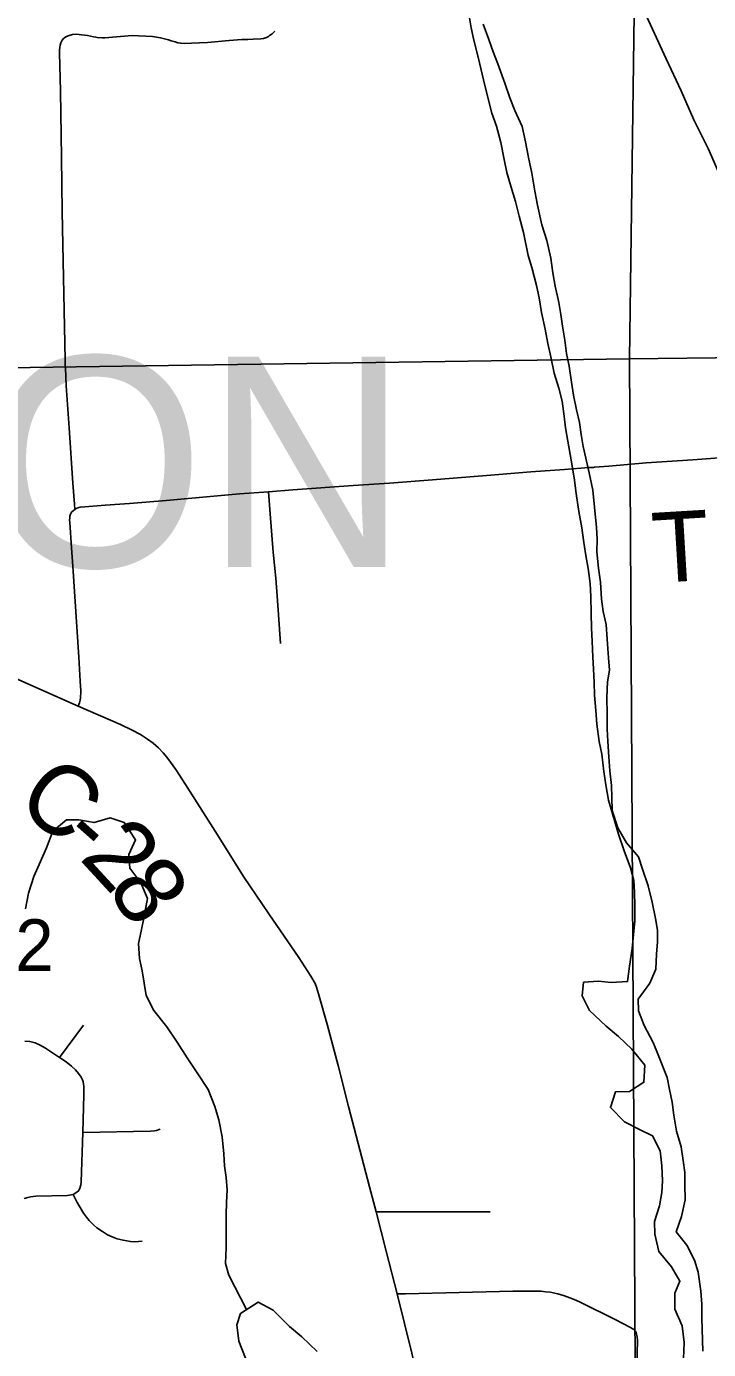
# Model space of a CAD drawing. Extents: x -87 to 2145, y -2128 to 440.
# Drawn here: x -42.301 to -41.749, y -694.892 to -693.821 of the extents above; entities that cross this region are included whole.
import ezdxf

# ---------------------------------------------------------------- set-up
doc = ezdxf.new("R2010")
doc.units = 0
for name, color, linetype in [('GM_X_City_Street', 7, 'Continuous'), ('GM_X_County_Road', 7, 'Continuous'), ('GM_X_County_Road_Text', 7, 'Continuous'), ('GM_X_Minor_Lake', 7, 'Continuous'), ('GM_X_Minor_River', 7, 'Continuous'), ('GM_X_Section', 7, 'Continuous'), ('GM_X_Section_Text', 7, 'Continuous'), ('GM_X_State_Route', 7, 'Continuous'), ('GM_X_Township_Road', 7, 'Continuous'), ('GM_X_Township_Road_Text', 7, 'Continuous'), ('GM_X_Township_Text', 7, 'Continuous')]:
    doc.layers.add(name, color=color, linetype=linetype)

msp = doc.modelspace()

# ---------------------------------------------------------------- linework, layer by layer
at = {"layer": 'GM_X_City_Street'}
msp.add_line((-42.2744, -694.656), (-42.2552, -694.6298), dxfattribs=at)
for points in [[(-42.3026, -694.6427), (-42.2985, -694.643), (-42.2942, -694.6441), (-42.2906, -694.6456), (-42.2858, -694.6483), (-42.2744, -694.656), (-42.2692, -694.6595), (-42.2648, -694.663), (-42.2616, -694.666), (-42.2592, -694.6688), (-42.257, -694.6717), (-42.2559, -694.6739), (-42.2553, -694.6757), (-42.2549, -694.6794), (-42.2549, -694.6862), (-42.2557, -694.7167), (-42.257, -694.7565), (-42.2573, -694.7591), (-42.258, -694.7616), (-42.259, -694.7635), (-42.2606, -694.765), (-42.2634, -694.7667), (-42.268, -694.7676), (-42.2937, -694.7683), (-42.298, -694.7687), (-42.3003, -694.7692), (-42.3031, -694.7702)], [(-42.2557, -694.7167), (-42.2008, -694.7156), (-42.1977, -694.7154), (-42.1959, -694.715), (-42.1931, -694.7139)], [(-42.2634, -694.7667), (-42.2601, -694.7733), (-42.2579, -694.7774), (-42.2552, -694.782), (-42.2528, -694.7851), (-42.2504, -694.7878), (-42.2471, -694.7913), (-42.2443, -694.7937), (-42.2398, -694.7969), (-42.2356, -694.7994), (-42.2318, -694.8012), (-42.2278, -694.8027), (-42.223, -694.8039), (-42.217, -694.8049), (-42.2134, -694.8051), (-42.2106, -694.805), (-42.2077, -694.8045)], [(-42.0182, -694.7808), (-42.0053, -694.7808), (-41.9257, -694.7809)], [(-42.0012, -694.8474), (-41.9944, -694.8473), (-41.9075, -694.8451), (-41.8889, -694.845), (-41.8846, -694.8452), (-41.881, -694.8456), (-41.8771, -694.846), (-41.871, -694.8473), (-41.8657, -694.8489), (-41.8613, -694.8506), (-41.8564, -694.8525), (-41.8525, -694.8544), (-41.8246, -694.8681), (-41.8121, -694.8745), (-41.8095, -694.8762)], [(-41.8072, -694.9165), (-41.8064, -694.8847), (-41.8067, -694.882), (-41.8072, -694.88), (-41.8076, -694.8787), (-41.8082, -694.8776), (-41.8095, -694.8762)]]:
    msp.add_lwpolyline(points, dxfattribs=at)
at = {"layer": 'GM_X_County_Road'}
for points in [[(-42.3424, -694.3346), (-42.2952, -694.3554), (-42.2593, -694.3714)], [(-42.2593, -694.3714), (-42.2252, -694.3863), (-42.2158, -694.3908), (-42.209, -694.3943), (-42.2032, -694.398), (-42.1987, -694.4014), (-42.1944, -694.4052), (-42.1905, -694.4092), (-42.1876, -694.4126), (-42.1846, -694.4166), (-42.1804, -694.4227), (-42.1726, -694.4347), (-42.1466, -694.4757), (-42.1256, -694.5093), (-42.1049, -694.5395), (-42.0807, -694.5749), (-42.0709, -694.5901), (-42.0675, -694.596)], [(-42.0675, -694.596), (-42.0664, -694.5989), (-42.0647, -694.6043), (-42.0576, -694.6301), (-42.0489, -694.6625), (-42.0404, -694.6956), (-42.0234, -694.7605), (-42.0182, -694.7808)], [(-42.0182, -694.7808), (-42.0101, -694.8126), (-42.0012, -694.8474)], [(-42.0012, -694.8474), (-41.9832, -694.9193), (-41.9763, -694.9476), (-41.9744, -694.9554), (-41.973, -694.9594), (-41.9714, -694.9626), (-41.9697, -694.9651), (-41.9677, -694.9672), (-41.9664, -694.9684), (-41.9634, -694.9702), (-41.9595, -694.9718), (-41.9536, -694.9734), (-41.925, -694.979), (-41.9207, -694.9799), (-41.917, -694.9809), (-41.9105, -694.9831), (-41.9019, -694.9868), (-41.8288, -695.021)]]:
    msp.add_lwpolyline(points, dxfattribs=at)
at = {"layer": 'GM_X_Minor_Lake'}
for points in [[(-41.9432, -693.8108), (-41.9412, -693.8222), (-41.9391, -693.8321), (-41.9356, -693.8458), (-41.9311, -693.8642), (-41.9279, -693.8775), (-41.9244, -693.8912), (-41.9208, -693.9016), (-41.9173, -693.9149), (-41.9146, -693.9287), (-41.9122, -693.9393), (-41.909, -693.9504), (-41.9054, -693.9626), (-41.9023, -693.9745), (-41.8988, -693.9878), (-41.895, -694.0065), (-41.8921, -694.0161), (-41.8883, -694.0306), (-41.8862, -694.0408), (-41.8842, -694.0527), (-41.8814, -694.066), (-41.879, -694.0778), (-41.8766, -694.0885), (-41.8739, -694.1018), (-41.8703, -694.114), (-41.8675, -694.1244), (-41.8659, -694.1365), (-41.8649, -694.146), (-41.8629, -694.1567), (-41.8602, -694.1723), (-41.8578, -694.1864), (-41.8562, -694.1993), (-41.8539, -694.2138), (-41.8515, -694.2271), (-41.8502, -694.237), (-41.8485, -694.2477), (-41.8465, -694.2599), (-41.8449, -694.272), (-41.8444, -694.2827), (-41.8439, -694.296), (-41.8438, -694.3081), (-41.8433, -694.3187), (-41.8428, -694.3316), (-41.8422, -694.3411), (-41.8417, -694.3521), (-41.8412, -694.3624), (-41.8403, -694.3749), (-41.8394, -694.3859), (-41.8375, -694.4), (-41.8354, -694.4103), (-41.8338, -694.4244), (-41.8321, -694.435), (-41.8301, -694.4476), (-41.8266, -694.4594), (-41.822, -694.4751), (-41.8173, -694.4885), (-41.8123, -694.5023), (-41.8095, -694.5126), (-41.8089, -694.5221), (-41.8088, -694.5327), (-41.8087, -694.5452), (-41.8097, -694.5562), (-41.8107, -694.5675), (-41.8129, -694.5819), (-41.8147, -694.5944), (-41.8277, -694.5952), (-41.838, -694.5942), (-41.8502, -694.595), (-41.8512, -694.606), (-41.8453, -694.6179), (-41.8319, -694.6304), (-41.8218, -694.6389)], [(-41.7681, -694.759), (-41.7683, -694.7491), (-41.7696, -694.7392), (-41.7712, -694.7282), (-41.7748, -694.7156), (-41.7771, -694.7026), (-41.7784, -694.692), (-41.7805, -694.6817), (-41.7826, -694.6721), (-41.7898, -694.6538), (-41.7937, -694.6438), (-41.801, -694.63), (-41.8057, -694.6181), (-41.8059, -694.6086), (-41.7965, -694.5956), (-41.7917, -694.5843), (-41.791, -694.5722), (-41.7904, -694.5623), (-41.7902, -694.5529), (-41.7919, -694.5433), (-41.7946, -694.53), (-41.7978, -694.517), (-41.8024, -694.5033), (-41.8056, -694.4933), (-41.8153, -694.4821), (-41.8223, -694.4698), (-41.8269, -694.456), (-41.8274, -694.4454), (-41.8276, -694.4355), (-41.8288, -694.4237), (-41.8297, -694.4123), (-41.8306, -694.3998), (-41.8311, -694.3899), (-41.8312, -694.3778), (-41.8313, -694.3645), (-41.8307, -694.3516), (-41.8293, -694.3422), (-41.8299, -694.3323), (-41.831, -694.3171), (-41.8319, -694.3053), (-41.8344, -694.2947), (-41.8357, -694.2848), (-41.8365, -694.2711), (-41.8381, -694.2597), (-41.8394, -694.2464), (-41.8391, -694.2362), (-41.8397, -694.2267), (-41.8412, -694.2103), (-41.8428, -694.1966), (-41.8456, -694.1825), (-41.8504, -694.1612), (-41.8521, -694.1513), (-41.8534, -694.1418), (-41.8559, -694.1315), (-41.8583, -694.1196), (-41.8599, -694.109), (-41.8619, -694.096), (-41.864, -694.0858), (-41.8653, -694.0751), (-41.8673, -694.0637), (-41.8686, -694.0542), (-41.8703, -694.0446), (-41.8731, -694.0313), (-41.8751, -694.0206), (-41.8767, -694.0085), (-41.8799, -693.9943), (-41.8841, -693.9817), (-41.8876, -693.9657), (-41.8896, -693.9543), (-41.892, -693.9398), (-41.8947, -693.9272), (-41.8971, -693.9143), (-41.8999, -693.9021), (-41.9057, -693.889), (-41.91, -693.8787), (-41.914, -693.8668), (-41.9197, -693.8511), (-41.9233, -693.8416), (-41.9269, -693.8316), (-41.9316, -693.819)], [(-41.8218, -694.6389), (-41.811, -694.6491), (-41.8006, -694.6622), (-41.8013, -694.6759), (-41.8129, -694.6835), (-41.8243, -694.6836), (-41.8284, -694.6964), (-41.8169, -694.7081), (-41.8048, -694.7141), (-41.7943, -694.7193), (-41.7881, -694.7316), (-41.7868, -694.7437), (-41.7863, -694.7559), (-41.7869, -694.7653), (-41.7887, -694.7759), (-41.7928, -694.7887), (-41.7926, -694.799), (-41.7891, -694.8131), (-41.7791, -694.8255), (-41.7721, -694.837), (-41.7762, -694.8468), (-41.7764, -694.8597), (-41.7703, -694.8731), (-41.7687, -694.8868), (-41.7693, -694.8997)], [(-41.7536, -694.8936), (-41.7545, -694.867), (-41.7543, -694.8557), (-41.7552, -694.845), (-41.7575, -694.8298), (-41.7603, -694.8199), (-41.7665, -694.8079), (-41.7751, -694.7971), (-41.771, -694.7847), (-41.768, -694.7711), (-41.7681, -694.759)], [(-42.0659, -694.8939), (-42.0782, -694.8822), (-42.0883, -694.8736), (-42.1014, -694.8604), (-42.1138, -694.854), (-42.1281, -694.8631), (-42.131, -694.8725), (-42.1293, -694.8855), (-42.1239, -694.8993)]]:
    msp.add_lwpolyline(points, dxfattribs=at)
at = {"layer": 'GM_X_Minor_River'}
for points in [[(-42.3021, -694.5356), (-42.2996, -694.5228), (-42.2954, -694.5092), (-42.291, -694.4995), (-42.285, -694.486), (-42.2798, -694.4725), (-42.2689, -694.4633), (-42.259, -694.4635), (-42.2465, -694.4657), (-42.2334, -694.4619), (-42.2221, -694.4656), (-42.2129, -694.4795), (-42.2185, -694.4915), (-42.2176, -694.5025), (-42.2087, -694.5145), (-42.2033, -694.5271)], [(-42.2033, -694.5271), (-42.2059, -694.5418), (-42.2084, -694.5535), (-42.2106, -694.5637), (-42.2097, -694.5758), (-42.2076, -694.5858), (-42.2043, -694.6056), (-42.1981, -694.6179), (-42.1877, -694.631), (-42.1792, -694.6434), (-42.1711, -694.6561), (-42.163, -694.6684), (-42.1541, -694.6819), (-42.1487, -694.6957), (-42.1456, -694.7064), (-42.1428, -694.7201), (-42.1416, -694.7338), (-42.141, -694.7437), (-42.1397, -694.7532), (-42.1388, -694.7631), (-42.1394, -694.7733), (-42.1396, -694.7832), (-42.1395, -694.7961), (-42.1395, -694.8097), (-42.1401, -694.8226), (-42.1373, -694.8322), (-42.1232, -694.86)]]:
    msp.add_lwpolyline(points, dxfattribs=at)
at = {"layer": 'GM_X_Section'}
for points in [[(-42.8008, -693.0943), (-41.7996, -693.0924), (-41.8129, -694.0902), (-42.8025, -694.1044), (-42.8334, -693.0959)], [(-41.8129, -694.0902), (-41.8074, -695.0971), (-42.8144, -695.0901), (-42.8025, -694.1044)]]:
    msp.add_lwpolyline(points, close=True, dxfattribs=at)
for points in [[(-41.6507, -694.0882), (-41.8129, -694.0902), (-41.7996, -693.0924)], [(-40.865, -695.1107), (-41.8074, -695.0971), (-41.8129, -694.0902), (-41.6507, -694.0882)]]:
    msp.add_lwpolyline(points, dxfattribs=at)
at = {"layer": 'GM_X_State_Route'}
msp.add_lwpolyline([(-41.6871, -694.0581), (-41.691, -694.049), (-41.6954, -694.0394), (-41.7045, -694.0189), (-41.7211, -693.9828), (-41.7388, -693.9438), (-41.7494, -693.9199), (-41.7608, -693.8965), (-41.7711, -693.8732), (-41.7833, -693.8473), (-41.8038, -693.8027)], dxfattribs=at)
at = {"layer": 'GM_X_Township_Road'}
for p, q in [((-41.8657, -694.1798), (-41.8459, -694.1782)), ((-41.8459, -694.1782), (-41.8422, -694.178))]:
    msp.add_line(p, q, dxfattribs=at)
for points in [[(-42.2622, -694.212), (-42.2625, -694.2077), (-42.2638, -694.1907), (-42.2666, -694.146), (-42.2691, -694.112), (-42.2698, -694.0973), (-42.2699, -694.0955), (-42.2699, -694.094), (-42.27, -694.0924), (-42.27, -694.0909), (-42.2723, -693.9709), (-42.2729, -693.9271), (-42.2738, -693.8734), (-42.2745, -693.8424), (-42.2745, -693.8401), (-42.2742, -693.8378), (-42.2739, -693.836), (-42.2734, -693.8341), (-42.2723, -693.8321), (-42.2709, -693.8305), (-42.269, -693.8292), (-42.2667, -693.8282), (-42.2641, -693.8276), (-42.2606, -693.8273), (-42.2567, -693.8277), (-42.2518, -693.8284), (-42.247, -693.8294), (-42.2451, -693.8297), (-42.2439, -693.8299), (-42.2397, -693.8301), (-42.2377, -693.8301), (-42.2158, -693.8284), (-42.2105, -693.8285), (-42.2045, -693.8288), (-42.1991, -693.8291), (-42.1927, -693.8302), (-42.1883, -693.8313), (-42.1862, -693.8318), (-42.184, -693.8325), (-42.181, -693.8335), (-42.1788, -693.8341), (-42.1764, -693.8346), (-42.1735, -693.8348), (-42.1676, -693.8346), (-42.1547, -693.834), (-42.1372, -693.8323), (-42.127, -693.8316), (-42.1221, -693.8314), (-42.1177, -693.8312), (-42.1116, -693.8309), (-42.1093, -693.8306), (-42.1078, -693.8302), (-42.1068, -693.8299), (-42.1053, -693.829), (-42.1044, -693.8284), (-42.1032, -693.8276), (-42.1024, -693.827), (-42.1013, -693.8259), (-42.1001, -693.8248)], [(-41.8296, -694.177), (-41.7996, -694.1743), (-41.7618, -694.1718), (-41.7222, -694.169), (-41.7151, -694.1686), (-41.7106, -694.1682), (-41.7063, -694.1678), (-41.7018, -694.1674), (-41.6983, -694.167), (-41.6944, -694.1665), (-41.6918, -694.1659), (-41.6893, -694.1654), (-41.6862, -694.1647), (-41.683, -694.1637), (-41.6787, -694.1626), (-41.668, -694.1599), (-41.6606, -694.158), (-41.6556, -694.1567)], [(-42.1052, -694.1977), (-42.0856, -694.1961), (-42.0368, -694.1927), (-42.0072, -694.1907), (-41.9725, -694.1881), (-41.9221, -694.184), (-41.8928, -694.1817), (-41.8657, -694.1798)], [(-41.8422, -694.178), (-41.8413, -694.1779), (-41.8296, -694.177)], [(-42.2622, -694.212), (-42.2611, -694.2113), (-42.2598, -694.2108), (-42.2577, -694.2103), (-42.2541, -694.21), (-42.2375, -694.2087), (-42.2179, -694.2073), (-42.1882, -694.2049), (-42.1287, -694.1995), (-42.1052, -694.1977)], [(-42.0955, -694.3207), (-42.0981, -694.2859), (-42.0994, -694.2677), (-42.1014, -694.2468), (-42.104, -694.2157), (-42.1052, -694.1977)], [(-42.2593, -694.3714), (-42.2583, -694.3686), (-42.2577, -694.3664), (-42.2576, -694.3646), (-42.2574, -694.363), (-42.2573, -694.3615), (-42.2573, -694.3603), (-42.2573, -694.3589), (-42.2577, -694.3511), (-42.259, -694.3318), (-42.262, -694.2825), (-42.2638, -694.2579), (-42.2647, -694.2431), (-42.2663, -694.2226), (-42.2664, -694.2206), (-42.2663, -694.2192), (-42.2661, -694.2175), (-42.2657, -694.2159), (-42.2648, -694.2144), (-42.2632, -694.2128), (-42.2622, -694.212)]]:
    msp.add_lwpolyline(points, dxfattribs=at)

# ---------------------------------------------------------------- texts
at = {"layer": 'GM_X_County_Road_Text'}
for s, rotation, p in [('C', 321.7358, (-42.3117, -694.452)), ('-', 318.5402, (-42.2757, -694.4803)), ('2', 312.6038, (-42.2593, -694.4947)), ('8', 304.2587, (-42.237, -694.5187))]:
    msp.add_text(s, height=0.0568, rotation=rotation, dxfattribs=at).set_placement(p)
at = {"layer": 'GM_X_Section_Text'}
msp.add_text('12', height=0.04186, rotation=0, dxfattribs=at).set_placement((-42.3415, -694.5858))
at = {"layer": 'GM_X_Township_Road_Text'}
msp.add_text('T', height=0.0568, rotation=3.4175, dxfattribs=at).set_placement((-41.7931, -694.2717))
at = {"layer": 'GM_X_Township_Text'}
msp.add_text('WASHINGTON', height=0.17045, rotation=0, dxfattribs=at).set_placement((-43.5623, -694.2587))

doc.saveas('drawing.dxf')
